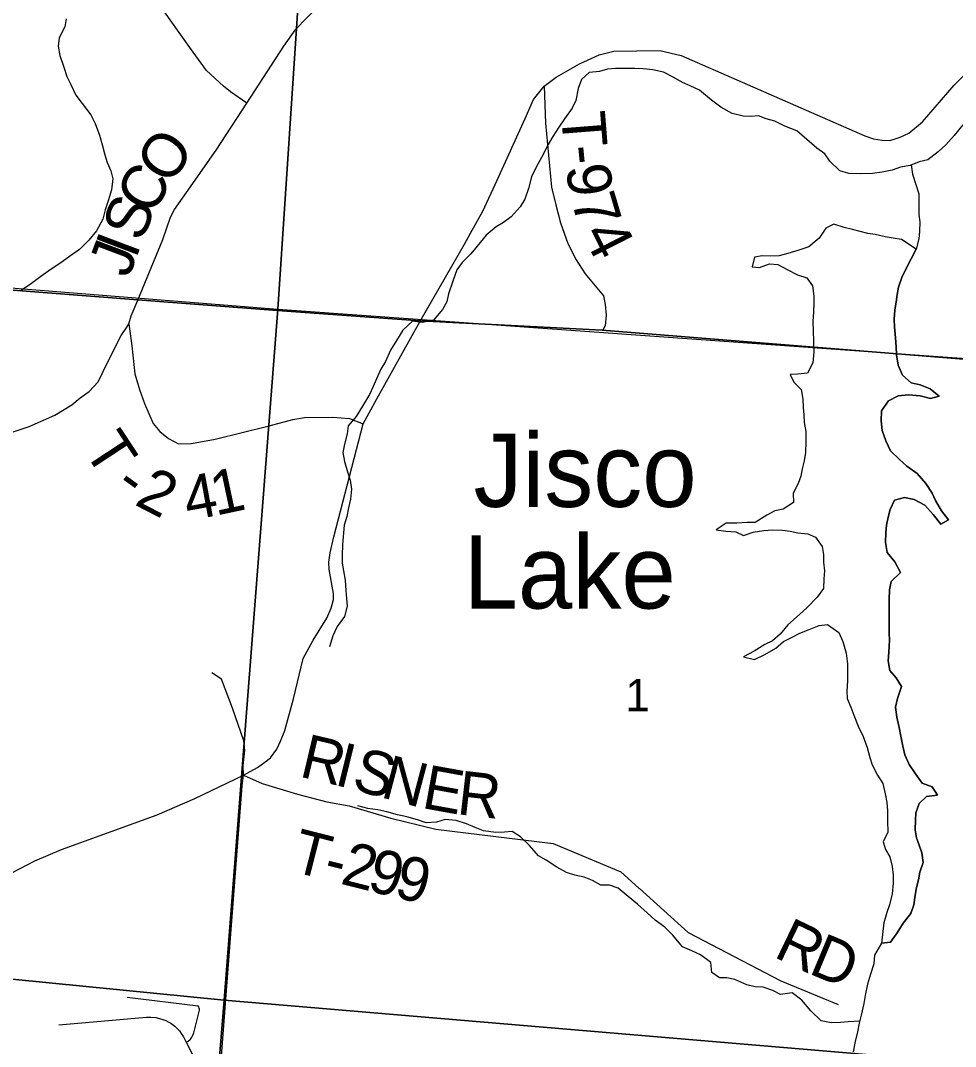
# Model space of a CAD drawing. Extents: x 0 to 34, y 0 to 22.
# Drawn here: x 24.965 to 26.174, y 19.052 to 20.378 of the extents above; entities that cross this region are included whole.
import ezdxf

# ---------------------------------------------------------------- set-up
doc = ezdxf.new("R2010")
doc.units = 0
for name, color, linetype in [('GM_X_Corporation', 7, 'Continuous'), ('GM_X_County_Road', 7, 'Continuous'), ('GM_X_County_Road_Text', 7, 'Continuous'), ('GM_X_Minor_Lake', 7, 'Continuous'), ('GM_X_Minor_Lake_Text', 7, 'Continuous'), ('GM_X_Minor_River', 7, 'Continuous'), ('GM_X_Section_Text', 7, 'Continuous'), ('GM_X_State_Route', 7, 'Continuous'), ('GM_X_Township_Road', 7, 'Continuous'), ('GM_X_Township_Road_Text', 7, 'Continuous')]:
    doc.layers.add(name, color=color, linetype=linetype)

msp = doc.modelspace()

# ---------------------------------------------------------------- linework, layer by layer
at = {"layer": 'GM_X_Corporation'}
for points in [[(26.3743, 20.9), (23.5167, 20.9), (23.5167, 20.1476), (23.8215, 20.1257), (24.2296, 20.084), (24.3889, 20.0736), (25.117, 20.0172), (25.2916, 20.0037), (25.482, 19.99), (25.7174, 19.9778), (26.3029, 19.931), (26.3351, 20.3683)], [(25.3573, 20.9), (24.4541, 20.9), (24.3968, 20.0768), (25.2979, 20.0049)], [(26.378, 20.9), (25.3573, 20.9), (25.2979, 20.0049), (26.302, 19.9328)], [(24.3968, 20.0768), (25.2979, 20.0049), (25.2286, 19.1118), (24.145, 19.219), (24.147, 19.2629), (24.2381, 20.0885)], [(26.302, 19.9328), (26.2267, 19.0272), (25.2286, 19.1118), (25.2979, 20.0049)]]:
    msp.add_lwpolyline(points, close=True, dxfattribs=at)
for points in [[(26.1825, 18.4635), (26.1926, 18.5708), (26.207, 18.8068), (26.2271, 19.0168), (26.2277, 19.0233), (26.2281, 19.0286), (26.3029, 19.931), (25.7174, 19.9778), (25.482, 19.99), (25.2916, 20.0037), (25.117, 20.0172), (24.3889, 20.0736), (24.2296, 20.084), (23.8215, 20.1257), (23.5167, 20.1476), (23.5167, 14.1), (25.8273, 14.1), (25.8671, 14.5774), (25.9626, 15.7291)], [(24.656, 18.1575), (24.0929, 18.2038), (24.145, 19.219), (25.2286, 19.1118), (25.1756, 18.4635)], [(25.1756, 18.4635), (25.2286, 19.1118), (26.2267, 19.0272), (26.2169, 18.8995), (26.1832, 18.4635)]]:
    msp.add_lwpolyline(points, dxfattribs=at)
at = {"layer": 'GM_X_County_Road'}
for points in [[(25.2581, 20.2711), (25.3057, 20.3451), (25.3211, 20.367), (25.3495, 20.3964), (25.4138, 20.455), (25.4611, 20.4877), (25.4877, 20.4997), (25.5761, 20.5175), (25.6105, 20.5241), (25.6487, 20.5333), (25.723, 20.5524), (25.7304, 20.5544), (25.7524, 20.5617), (25.7731, 20.5722), (25.8117, 20.5997), (25.8576, 20.6409), (25.8752, 20.6681), (25.9079, 20.7222), (25.9386, 20.7725), (25.9523, 20.7916), (25.9606, 20.8013), (26.0006, 20.8252), (26.0414, 20.8523), (26.1102, 20.9)], [(25.2581, 20.2711), (25.2366, 20.286), (25.2278, 20.2932), (25.2057, 20.3136), (25.1884, 20.337), (25.1568, 20.3822), (25.0954, 20.4698), (25.0807, 20.4992), (25.0865, 20.6324)], [(25.18, 20.1558), (25.2183, 20.2103), (25.2581, 20.2711)], [(25.1027, 19.9817), (25.1055, 19.9858), (25.1084, 19.9964), (25.1172, 20.0167), (25.1493, 20.0952), (25.1591, 20.1241), (25.1646, 20.1339), (25.18, 20.1558)], [(24.9132, 19.832), (24.9766, 19.8534), (25.0098, 19.868), (25.0317, 19.8814), (25.0425, 19.8902), (25.0542, 19.8987), (25.0659, 19.9111), (25.0779, 19.9359), (25.0953, 19.9709), (25.1027, 19.9817)], [(25.1954, 18.6891), (25.1997, 18.7047), (25.201, 18.7398), (25.2023, 18.7782), (25.2153, 18.9232), (25.2205, 18.9776), (25.2517, 19.3889), (25.2535, 19.4025)]]:
    msp.add_lwpolyline(points, dxfattribs=at)
at = {"layer": 'GM_X_Minor_Lake'}
for points in [[(26.1234, 20.0824), (26.1041, 20.0949), (26.0935, 20.0968), (26.0833, 20.0983), (26.0704, 20.1014), (26.0606, 20.1029), (26.0507, 20.1052), (26.0409, 20.1079), (26.0303, 20.1105), (26.0167, 20.1147), (26.0065, 20.1098), (25.9978, 20.0969), (25.9845, 20.0855), (25.9701, 20.0806), (25.9573, 20.0769), (25.9463, 20.0738), (25.9346, 20.0735), (25.924, 20.0739), (25.9141, 20.072), (25.9111, 20.0598), (25.9209, 20.0587), (25.9338, 20.0636), (25.9444, 20.0625), (25.9565, 20.0564), (25.9697, 20.0495), (25.9818, 20.0454), (25.9894, 20.0351), (25.9909, 20.0218), (25.9908, 20.0124), (25.9905, 20.0017), (25.9897, 19.9892), (25.99, 19.9767), (25.9904, 19.9638), (25.9908, 19.9498), (25.9896, 19.9354), (25.9828, 19.9221), (25.9703, 19.921), (25.9605, 19.9206), (25.965, 19.9104), (25.9744, 19.9009), (25.9767, 19.8884), (25.977, 19.8778), (25.9778, 19.8683), (25.9785, 19.8584), (25.9808, 19.8467), (25.9808, 19.8334), (25.98, 19.8197), (25.9785, 19.8088), (25.9758, 19.7985), (25.9743, 19.789), (25.9705, 19.7796), (25.9644, 19.7671), (25.9648, 19.7549), (25.9511, 19.7462), (25.9406, 19.7443), (25.93, 19.7387), (25.9152, 19.7292), (25.9046, 19.7292), (25.8913, 19.7285), (25.8777, 19.7285), (25.8645, 19.7198), (25.877, 19.7179), (25.8902, 19.7171), (25.9, 19.7125), (25.9125, 19.7167), (25.9265, 19.7189), (25.9375, 19.7197), (25.9504, 19.7193), (25.9602, 19.7178), (25.9704, 19.7159), (25.9833, 19.7143), (25.9931, 19.7101), (26.0018, 19.698), (26.0033, 19.6878), (26.0033, 19.6779), (26.0048, 19.6665), (26.004, 19.6563), (26.0036, 19.6438), (25.9953, 19.6328), (25.9824, 19.6192), (25.9725, 19.6101), (25.9574, 19.5968), (25.9475, 19.5847), (25.9377, 19.576), (25.9278, 19.5714), (25.9138, 19.5627), (25.9002, 19.5555), (25.9142, 19.5521), (25.9278, 19.5585), (25.9418, 19.5669), (25.9517, 19.5752), (25.9619, 19.5805), (25.9729, 19.5862), (25.985, 19.5907), (25.9979, 19.596), (26.0085, 19.5971), (26.0232, 19.5869), (26.0285, 19.5751), (26.0326, 19.5603), (26.0345, 19.5463), (26.0345, 19.5243)], [(26.0901, 19.1865), (26.0988, 19.1986), (26.1065, 19.211), (26.1164, 19.2238), (26.1203, 19.2348), (26.1219, 19.2473), (26.1235, 19.2572), (26.1262, 19.267), (26.1281, 19.2772), (26.1324, 19.2897), (26.1306, 19.3023), (26.1272, 19.3118), (26.1235, 19.3213), (26.1221, 19.3319), (26.1222, 19.3444), (26.1226, 19.3539), (26.1272, 19.366), (26.1368, 19.375), (26.1508, 19.3768), (26.144, 19.3875), (26.1312, 19.3921), (26.1222, 19.4043), (26.1143, 19.4161), (26.1084, 19.4287), (26.1058, 19.4401), (26.1032, 19.453), (26.1014, 19.464), (26.0981, 19.4773), (26.0967, 19.4902), (26.099, 19.5016), (26.1044, 19.5171), (26.0973, 19.5285), (26.0891, 19.538), (26.0872, 19.5502), (26.0881, 19.5616), (26.0889, 19.5771), (26.0882, 19.5866), (26.0885, 19.6185), (26.0882, 19.6294), (26.0886, 19.6423), (26.091, 19.6529), (26.1028, 19.6646), (26.0957, 19.6783), (26.0856, 19.6905), (26.0837, 19.7031), (26.0842, 19.7163), (26.085, 19.7258), (26.087, 19.736), (26.0897, 19.7459), (26.0951, 19.758), (26.108, 19.7613), (26.1208, 19.7589), (26.1344, 19.7516), (26.1453, 19.7394), (26.155, 19.7272), (26.1649, 19.7325), (26.1559, 19.7443), (26.1481, 19.7576), (26.144, 19.7671), (26.1357, 19.7797), (26.1245, 19.7923), (26.1113, 19.8019), (26.1015, 19.8106), (26.0902, 19.8217), (26.0839, 19.8347), (26.0794, 19.848), (26.078, 19.8605), (26.0785, 19.8737), (26.0876, 19.8866), (26.0998, 19.893), (26.1134, 19.8944), (26.1286, 19.8931), (26.1418, 19.8893), (26.1531, 19.8926), (26.1415, 19.9018), (26.1283, 19.9072), (26.1169, 19.9099), (26.1057, 19.9198), (26.1001, 19.9324), (26.0979, 19.9461), (26.0972, 19.9563), (26.0965, 19.9681), (26.0951, 19.9821), (26.0948, 19.9916), (26.0956, 20.0041), (26.0972, 20.0139), (26.0988, 20.0238), (26.1004, 20.0333), (26.1046, 20.0458), (26.1108, 20.0582), (26.1169, 20.0699), (26.1234, 20.0824)], [(26.0345, 19.5243), (26.0337, 19.511), (26.0341, 19.5016), (26.0386, 19.4902), (26.0427, 19.4799), (26.0484, 19.4659), (26.0548, 19.4526), (26.0601, 19.4382), (26.0635, 19.4253), (26.0665, 19.4158), (26.0733, 19.4025), (26.0801, 19.3919), (26.0831, 19.3783), (26.0853, 19.3673), (26.0861, 19.3563), (26.0861, 19.3434), (26.0864, 19.3286), (26.0807, 19.3161), (26.0834, 19.3066), (26.0894, 19.2971), (26.0924, 19.2846), (26.0935, 19.2732), (26.0935, 19.263), (26.092, 19.2493), (26.0886, 19.2349), (26.0855, 19.2251), (26.0814, 19.2114), (26.0783, 19.1854)], [(26.0783, 19.1854), (26.0901, 19.1865)]]:
    msp.add_lwpolyline(points, dxfattribs=at)
at = {"layer": 'GM_X_Minor_River'}
for points in [[(25.0243, 20.3801), (25.0227, 20.3699), (25.0151, 20.3559), (25.0142, 20.3449), (25.0161, 20.3331), (25.0212, 20.3179), (25.0253, 20.3058), (25.0302, 20.2955), (25.0369, 20.2818), (25.0451, 20.2708), (25.0564, 20.2563), (25.062, 20.2452), (25.0676, 20.23), (25.0713, 20.216), (25.0742, 20.2046), (25.0775, 20.1947), (25.082, 20.1837), (25.0846, 20.1734), (25.083, 20.1594), (25.0791, 20.1461), (25.0749, 20.1333), (25.0717, 20.1212), (25.0637, 20.1064), (25.0538, 20.094), (25.0416, 20.0823), (25.0287, 20.0729), (25.0161, 20.0642), (25.0051, 20.0567), (24.9914, 20.0473), (24.9796, 20.0383), (24.9648, 20.0282)], [(26.1835, 20.2432), (26.1725, 20.2296), (26.1618, 20.2172), (26.1515, 20.2085), (26.1382, 20.198), (26.1272, 20.1954), (26.1155, 20.1909), (26.1029, 20.1884), (26.0923, 20.1846), (26.0794, 20.1821), (26.0669, 20.1803), (26.0514, 20.18), (26.0363, 20.1805), (26.0246, 20.1836), (26.0118, 20.1962), (26.0051, 20.2057), (25.9949, 20.213), (25.9817, 20.2244), (25.9689, 20.2355), (25.9535, 20.2417), (25.9406, 20.2478), (25.9293, 20.2509), (25.9195, 20.2548), (25.9097, 20.2541), (25.8994, 20.2545), (25.8855, 20.2581), (25.8708, 20.2661), (25.8587, 20.2753), (25.8433, 20.2879), (25.8312, 20.2937), (25.821, 20.2979), (25.8101, 20.3044), (25.7965, 20.3113), (25.7826, 20.3145), (25.7701, 20.3157), (25.7595, 20.3161), (25.7496, 20.3162), (25.7345, 20.3159), (25.7243, 20.3152), (25.7137, 20.3123), (25.7004, 20.3108), (25.6905, 20.3018), (25.6863, 20.2904), (25.6831, 20.2749), (25.6785, 20.2647), (25.6686, 20.2511), (25.6613, 20.2402), (25.6537, 20.2281), (25.646, 20.2156), (25.641, 20.2047), (25.6326, 20.1895), (25.6261, 20.1759), (25.6222, 20.1608), (25.6172, 20.1472), (25.6111, 20.1374), (25.5996, 20.1245), (25.5897, 20.117), (25.5802, 20.1114), (25.5673, 20.1008), (25.5555, 20.0865), (25.5475, 20.0767), (25.5364, 20.0654), (25.5295, 20.0556), (25.5241, 20.0412), (25.5187, 20.0249), (25.5164, 20.0143), (25.511, 20.0045), (25.4992, 19.9906), (25.4848, 19.9876), (25.4719, 19.9896), (25.4598, 19.9779), (25.4513, 19.9643), (25.4437, 19.9519), (25.4372, 19.9375), (25.431, 19.9273), (25.4257, 19.9148), (25.4214, 19.905), (25.4164, 19.8948), (25.4076, 19.8797), (25.3992, 19.8664), (25.3889, 19.854), (25.3877, 19.8438), (25.3842, 19.8305), (25.3822, 19.8195), (25.3841, 19.8081), (25.3881, 19.7948), (25.3915, 19.7838), (25.3933, 19.7724), (25.3921, 19.7592), (25.3893, 19.7482), (25.387, 19.7368), (25.3839, 19.7255), (25.3818, 19.7008), (25.3813, 19.686), (25.3813, 19.6765), (25.3827, 19.6667), (25.3849, 19.6545), (25.3859, 19.6412)], [(26.1167, 20.1914), (26.1184, 20.1795), (26.1229, 20.1662), (26.1266, 20.1541), (26.1268, 20.1416), (26.1267, 20.1275), (26.1278, 20.1177), (26.1277, 20.1055), (26.1269, 20.096), (26.1234, 20.0824), (26.1169, 20.0699), (26.1108, 20.0582), (26.1046, 20.0458), (26.1004, 20.0333), (26.0988, 20.0238), (26.0972, 20.0139), (26.0956, 20.0041), (26.0948, 19.9916), (26.0951, 19.9821), (26.0965, 19.9681), (26.0972, 19.9563), (26.0979, 19.9461), (26.1001, 19.9324), (26.1057, 19.9198), (26.1169, 19.9099), (26.1283, 19.9072), (26.1415, 19.9018), (26.1531, 19.8926), (26.1418, 19.8893), (26.1286, 19.8931), (26.1134, 19.8944), (26.0998, 19.893), (26.0876, 19.8866), (26.0785, 19.8737), (26.078, 19.8605), (26.0794, 19.848), (26.0839, 19.8347), (26.0902, 19.8217), (26.1015, 19.8106), (26.1113, 19.8019), (26.1245, 19.7923), (26.1357, 19.7797), (26.144, 19.7671), (26.1481, 19.7576), (26.1559, 19.7443), (26.1649, 19.7325), (26.155, 19.7272), (26.1453, 19.7394), (26.1344, 19.7516), (26.1208, 19.7589), (26.108, 19.7613), (26.0951, 19.758), (26.0897, 19.7459), (26.087, 19.736), (26.085, 19.7258), (26.0842, 19.7163), (26.0837, 19.7031), (26.0856, 19.6905), (26.0957, 19.6783), (26.1028, 19.6646), (26.091, 19.6529), (26.0886, 19.6423), (26.0882, 19.6294), (26.0885, 19.6185), (26.0882, 19.5866), (26.0889, 19.5771), (26.0881, 19.5616), (26.0872, 19.5502), (26.0891, 19.538), (26.0973, 19.5285), (26.1044, 19.5171), (26.099, 19.5016), (26.0967, 19.4902), (26.0981, 19.4773), (26.1014, 19.464), (26.1032, 19.453), (26.1058, 19.4401), (26.1084, 19.4287), (26.1143, 19.4161), (26.1222, 19.4043), (26.1312, 19.3921), (26.144, 19.3875), (26.1508, 19.3768), (26.1368, 19.375), (26.1272, 19.366), (26.1226, 19.3539), (26.1222, 19.3444), (26.1221, 19.3319), (26.1235, 19.3213), (26.1272, 19.3118), (26.1306, 19.3023), (26.1324, 19.2897), (26.1281, 19.2772), (26.1262, 19.267), (26.1235, 19.2572), (26.1219, 19.2473), (26.1203, 19.2348), (26.1164, 19.2238), (26.1065, 19.211), (26.0988, 19.1986), (26.0901, 19.1865)], [(25.3859, 19.6412), (25.3866, 19.631), (25.3877, 19.6211), (25.3842, 19.6075), (25.3747, 19.5947), (25.3689, 19.5826), (25.3646, 19.5686)], [(26.0504, 19.0846), (26.0353, 19.0837), (26.0254, 19.0826), (26.0133, 19.0823), (26.0004, 19.0847), (25.9869, 19.098), (25.9753, 19.1114), (25.9629, 19.1209), (25.9477, 19.1191), (25.9379, 19.1241), (25.9254, 19.1284), (25.9152, 19.1288), (25.9043, 19.1316), (25.8888, 19.1385), (25.8786, 19.1405), (25.8688, 19.1405), (25.859, 19.1474), (25.8576, 19.1603), (25.8444, 19.1703), (25.8334, 19.1753), (25.821, 19.1807), (25.8086, 19.1955), (25.7985, 19.2062), (25.786, 19.215), (25.7755, 19.2246), (25.7631, 19.2356), (25.751, 19.2456), (25.7379, 19.2563), (25.7266, 19.2605), (25.7156, 19.2602), (25.7046, 19.2664), (25.6941, 19.2706), (25.682, 19.2733), (25.6714, 19.2768), (25.6586, 19.2837), (25.645, 19.2925), (25.6352, 19.2983), (25.6232, 19.3117), (25.6116, 19.3227), (25.601, 19.3296), (25.5912, 19.3289), (25.5798, 19.3282), (25.5639, 19.3306), (25.553, 19.3349), (25.5421, 19.3395), (25.5285, 19.3441), (25.5145, 19.3454), (25.5031, 19.3416), (25.4899, 19.341), (25.4785, 19.3448), (25.4649, 19.3487), (25.4528, 19.3514), (25.4389, 19.3549), (25.4272, 19.3577), (25.4143, 19.3593), (25.4015, 19.3628)], [(26.0901, 19.1865), (26.0783, 19.1854), (26.0695, 19.1699), (26.0683, 19.1586), (26.0644, 19.1453), (26.0602, 19.1321), (26.0574, 19.1177), (26.0555, 19.1074), (26.0523, 19.0923), (26.0496, 19.0817), (26.0473, 19.0707), (26.0445, 19.0582), (26.0418, 19.0449)]]:
    msp.add_lwpolyline(points, dxfattribs=at)
at = {"layer": 'GM_X_State_Route'}
for points in [[(25.5472, 20.1034), (25.5632, 20.1316), (25.5816, 20.1717), (25.6178, 20.2514), (25.6284, 20.2759), (25.6423, 20.2932), (25.6579, 20.3049), (25.688, 20.3222), (25.7136, 20.3339), (25.7325, 20.3383), (25.7919, 20.3393), (25.8196, 20.3331), (25.8982, 20.2985), (26.0568, 20.229), (26.068, 20.225), (26.0792, 20.2236), (26.0891, 20.2232), (26.096, 20.2253), (26.1027, 20.2272), (26.1139, 20.2326), (26.1315, 20.2471), (26.1722, 20.2946), (26.1913, 20.3137)], [(25.4084, 19.8568), (25.426, 19.8892), (25.4822, 19.9895), (25.5393, 20.0892), (25.5472, 20.1034)], [(24.954, 19.2762), (24.9839, 19.2919), (25.0185, 19.3062), (25.142, 19.3514), (25.1908, 19.3725), (25.2535, 19.4025), (25.2717, 19.4126), (25.2811, 19.4195), (25.2883, 19.4251), (25.2966, 19.4359), (25.3014, 19.4465), (25.3069, 19.4601), (25.3182, 19.5013), (25.3309, 19.5535), (25.3437, 19.5771), (25.3612, 19.6053), (25.367, 19.6185), (25.3698, 19.6297), (25.3698, 19.6374), (25.3644, 19.6686), (25.364, 19.678), (25.3658, 19.6898), (25.3704, 19.7108), (25.4084, 19.8568)]]:
    msp.add_lwpolyline(points, dxfattribs=at)
at = {"layer": 'GM_X_Township_Road'}
msp.add_line((25.1034, 19.1153), (25.1951, 19.1041), dxfattribs=at)
for points in [[(25.6423, 20.2932), (25.644, 20.2453), (25.6518, 20.1628), (25.6574, 20.1399), (25.6635, 20.1165), (25.6729, 20.0898), (25.6835, 20.0686), (25.6952, 20.0508), (25.7192, 20.0224), (25.721, 20.011), (25.7226, 19.9971), (25.721, 19.9835), (25.7176, 19.9773)], [(25.1055, 19.9858), (25.1091, 19.9575), (25.1133, 19.9214), (25.1193, 19.9012), (25.1257, 19.8828), (25.137, 19.8572), (25.1454, 19.847), (25.1566, 19.8376), (25.1697, 19.8307), (25.1865, 19.8311), (25.217, 19.8367), (25.287, 19.8542), (25.3175, 19.8624), (25.3326, 19.865), (25.3689, 19.8655), (25.3907, 19.8636), (25.4084, 19.8568)], [(25.2535, 19.4025), (25.2532, 19.4149), (25.2553, 19.4345), (25.2539, 19.447), (25.2392, 19.4893), (25.2251, 19.5264), (25.2127, 19.5347)], [(25.2535, 19.4025), (25.2779, 19.3919), (25.3235, 19.3778), (25.3613, 19.3682), (25.3903, 19.3629), (25.444, 19.3467), (25.5021, 19.3329), (25.654, 19.314), (25.7415, 19.2776), (25.7648, 19.2566), (25.7655, 19.2559)], [(25.7655, 19.2559), (25.8284, 19.1993), (25.9481, 19.1367), (26.0222, 19.1062)], [(25.1794, 19.0575), (25.1819, 19.0588), (25.1849, 19.0614), (25.1868, 19.0639), (25.1883, 19.0663), (25.1894, 19.0693), (25.1967, 19.0988), (25.1967, 19.0999), (25.1964, 19.1013), (25.1957, 19.1029), (25.1951, 19.1041)], [(25.015, 19.0796), (25.1282, 19.0895), (25.1339, 19.0897), (25.1402, 19.0891), (25.1449, 19.0881), (25.1495, 19.0867), (25.1532, 19.0853), (25.1564, 19.0838), (25.1598, 19.0817), (25.1647, 19.078), (25.1679, 19.075), (25.1707, 19.072), (25.1732, 19.0687), (25.1762, 19.0644), (25.1794, 19.0575), (25.2205, 18.9776)]]:
    msp.add_lwpolyline(points, dxfattribs=at)

# ---------------------------------------------------------------- texts
at = {"layer": 'GM_X_County_Road_Text'}
for s, rotation, p in [('O', 54.7134, (25.1576, 20.1635)), ('C', 60.3021, (25.1353, 20.1242)), ('S', 69.073, (25.1225, 20.0905)), ('I', 69.3133, (25.1143, 20.0687)), ('J', 69.3288, (25.1049, 20.0438))]:
    msp.add_text(s, height=0.0568, rotation=rotation, dxfattribs=at).set_placement(p)
at = {"layer": 'GM_X_Minor_Lake_Text'}
for s, rotation, p in [('Jisco', 0.0075, (25.551, 19.7493)), ('Lake', 0.0076, (25.538, 19.6179))]:
    msp.add_text(s, height=0.09469, rotation=rotation, dxfattribs=at).set_placement(p)
at = {"layer": 'GM_X_Section_Text'}
msp.add_text('1', height=0.0419, rotation=0, dxfattribs=at).set_placement((25.7475, 19.4851))
at = {"layer": 'GM_X_Township_Road_Text'}
for s, rotation, p in [('T', 274.4746, (25.6641, 20.2585)), ('-', 275.6004, (25.6675, 20.215)), ('9', 278.0322, (25.6701, 20.1893)), ('7', 286.4767, (25.6769, 20.146)), ('4', 296.9239, (25.6909, 20.1023)), ('T', 303.3209, (25.0458, 19.823)), ('-', 324.1437, (25.0846, 19.7713)), ('2', 332.7024, (25.1112, 19.7529)), ('4', 10.5279, (25.1818, 19.7312)), ('1', 12.0192, (25.2175, 19.7378)), ('R', 346.6889, (25.3243, 19.401)), ('I', 346.1342, (25.3695, 19.3903)), ('S', 344.4723, (25.3918, 19.3848)), ('N', 345.0898, (25.4293, 19.3744)), ('E', 349.6917, (25.4825, 19.3604)), ('R', 353.4029, (25.5283, 19.3522)), ('T', 345.7101, (25.3136, 19.2787)), ('2', 345.8055, (25.3775, 19.2625)), ('9', 346.0816, (25.4117, 19.2538)), ('-', 345.7238, (25.3548, 19.2683)), ('9', 346.837, (25.4465, 19.2452)), ('R', 334.3217, (25.9375, 19.1683)), ('D', 337.3483, (25.9825, 19.1468))]:
    msp.add_text(s, height=0.0568, rotation=rotation, dxfattribs=at).set_placement(p)

doc.saveas('drawing.dxf')
